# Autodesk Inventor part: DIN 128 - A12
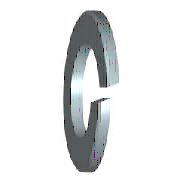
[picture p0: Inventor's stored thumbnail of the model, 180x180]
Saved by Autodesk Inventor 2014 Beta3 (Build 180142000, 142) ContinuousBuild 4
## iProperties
IsCustomPart: 0
Created: 2010-02
Part Number: DIN 128 - A12
Material: Steel, Mild
Description: Spring Washer
Document SubType Name: Modeling
Standard: DIN 128
Designer: Thom Tremblay
Standard Revision: 1994
Standards Organization: DIN
Language: en-US
Size Designation: A12
Categories: <MemberInstance><Categories><Category DisplayName="Fasteners" InternalName="e4da775c-781d-43d5-af7c-5136215cf5a6" Mnemonic="FSTN"><Category DisplayName="Washers
Density: 1 g/cm^3
Appearance: Steel
Author: Thom Tremblay
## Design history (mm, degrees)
sketch "Sketch1"
  geometry: C1 r 10.55 at (0, 0); C2 r 6.35 at (0, 0); 1 further point
  constraints: 2 centre point, 2 coincident
  dimensions: "d0" = 12.7 diameter of C2 (= SD1); "d1" = 21.1 diameter of C1 (= SD2)
extrude "Body" new body sketch "Sketch1" distance "d2" = 2.1 (= SD); taper "d3" = 0 deg
sketch "Sketch2"
  geometry: L1 (0, -6.35)-(0, 6.35) reference; L2 (2.1, 10.55)-(2.1, -10.55) reference; L3 (-1.2, 0)-(7.2, 0) reference; L4 (0, -0.42)-(2.1, 0.792); L5 (0, 0.42)-(2.1, 1.632)
  constraints: 4 end point, 4 point on line, 1 parallel
  dimensions: "d4" = 0.42 distance from line of L3 L4.start (= 0.2 x SD); "d5" = 0.42 distance from line of L3 L5.start (= 0.2 x SD); "d6" = 60 deg angle of L2 L4 (= FAWI)
extrude "Cut" cut sketch "Sketch2" stored distance "d7" = 2.1 (= SD); taper "d8" = 0 deg
workaxis "Work Axis1"
workplane "Work Plane1"
body "Solid1"
fillet "Fillet" dims "d13" = 1 (= R)
other parameters: "SD1" = 12.7 [user parameter; used in 1 equation term], "SD2" = 21.1 [user parameter; used in 1 equation term], "SD" = 2.1 [user parameter; used in 4 equation terms], "FAWI" = 60 deg [user parameter; used in 1 equation term], "d9" = 0, "d10" = 0, "d11" = 0, "d12" = 0, "R" = 1 [user parameter; used in 1 equation term], "NND" = 12 [user parameter]
